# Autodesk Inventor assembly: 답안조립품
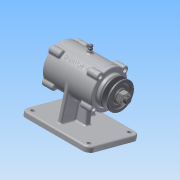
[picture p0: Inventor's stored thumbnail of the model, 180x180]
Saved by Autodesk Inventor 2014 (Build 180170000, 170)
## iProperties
Created: 2016-01
Part Number: 답안조립품
Document SubType Name: Assembly
Designer: Administrator
Author: Administrator
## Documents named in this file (10)
- C:\Users\Administrator\Desktop\460108V1001\답안조립품.iam
- C:\Users\Administrator\Desktop\460108V1001\1.본체.ipt
- C:\Users\Administrator\Desktop\460108V1001\커버2.ipt
- C:\Users\Administrator\Desktop\460108V1001\베어링 6204.ipt
- C:\Users\Administrator\Desktop\460108V1001\축.ipt
- C:\Users\Administrator\Desktop\460108V1001\니플 M 6 x 0.75.ipt
- C:\Users\Administrator\Desktop\460108V1001\커버.ipt
- C:\Users\Administrator\Desktop\460108V1001\키(4 x 4 x 12).ipt
- C:\Users\Administrator\Desktop\460108V1001\V-벨트풀리.ipt
- C:\Users\Administrator\Desktop\460108V1001\너트 M12x1.25.ipt
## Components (6 placed, 5 different names)
1. 1.본체:1
2. KS B 2023 6204 - 20 x 47 x 14:1
3. KS B 1311 (I) 4 x 4 x 12:1 — 각도:1, 각도:2, 각도:3
4. KS B 2023 6204 - 20 x 47 x 14:2
5. V-벨트풀리:1 — 각도:2, 각도:3
6. KS B 1012 클래스 1 일반 - 미터 M12x1.25:1
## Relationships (3: Angle 3)
- 각도:1 [Angle]: KS B 1311 (I) 4 x 4 x 12:1
- 각도:2 [Angle]: KS B 1311 (I) 4 x 4 x 12:1 ↔ V-벨트풀리:1
- 각도:3 [Angle]: KS B 1311 (I) 4 x 4 x 12:1 ↔ V-벨트풀리:1
